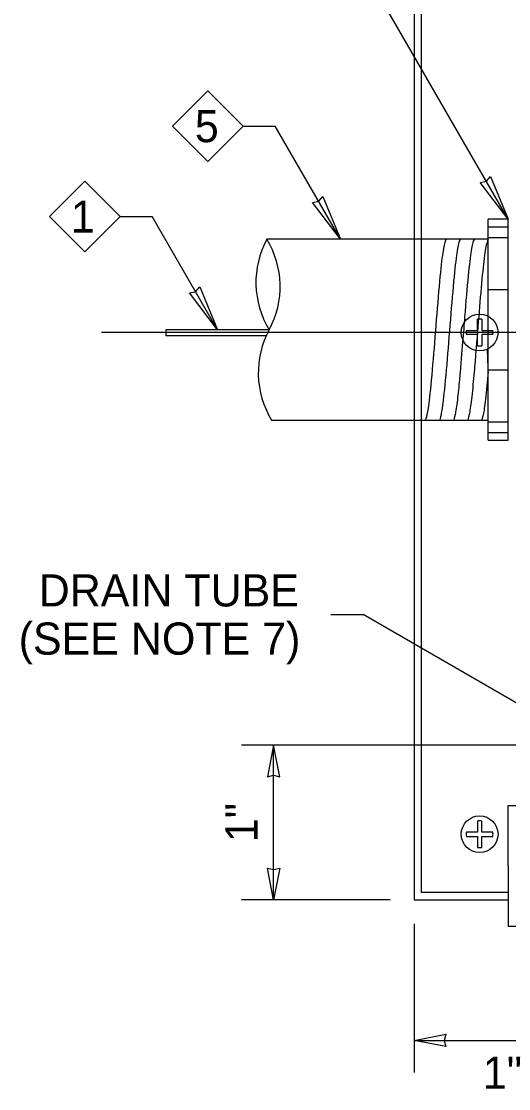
# Model space of a CAD drawing. Extents: x 99862 to 103680, y 99470 to 102076.
# Drawn here: x 101053 to 101296, y 101269 to 101800 of the extents above; entities that cross this region are included whole.
import ezdxf

# ---------------------------------------------------------------- set-up
doc = ezdxf.new("R2010")
doc.units = 0
for name, color, linetype in [('Level 1', 7, 'Continuous'), ('Level 10', 7, 'Continuous'), ('Level 15', 7, 'Continuous'), ('Level 20', 7, 'Continuous'), ('Level 4', 7, 'Continuous'), ('Level 6', 7, 'Continuous'), ('Level 9', 7, 'Continuous')]:
    doc.layers.add(name, color=color, linetype=linetype)

msp = doc.modelspace()

# ---------------------------------------------------------------- linework, layer by layer
at = {"layer": 'Level 1'}
for p, q in [((101248.49, 101927.58), (101248.49, 101362.86)), ((101252.13, 101675.72), (101252.13, 101923.94)), ((101252.13, 101366.5), (101252.13, 101675.72)), ((101295.35, 101366.5), (101252.13, 101366.5)), ((101248.49, 101362.86), (101295.35, 101362.86))]:
    msp.add_line(p, q, dxfattribs=at)
at = {"layer": 'Level 10'}
for p, q in [((101280.05, 101646.21), (101280.05, 101651.78)), ((101282.11, 101651.78), (101282.11, 101646.21)), ((101274.48, 101646.21), (101280.05, 101646.21)), ((101280.05, 101644.15), (101274.48, 101644.15)), ((101280.05, 101638.58), (101280.05, 101644.15)), ((101282.11, 101646.21), (101287.68, 101646.21)), ((101287.68, 101644.15), (101282.11, 101644.15)), ((101282.11, 101644.15), (101282.11, 101638.58)), ((101280.05, 101402.06), (101280.05, 101396.49)), ((101282.11, 101396.49), (101282.11, 101402.06)), ((101280.05, 101396.49), (101274.48, 101396.49)), ((101274.48, 101394.42), (101280.05, 101394.42)), ((101280.05, 101394.42), (101280.05, 101388.86)), ((101287.68, 101396.49), (101282.11, 101396.49)), ((101282.11, 101388.86), (101282.11, 101394.42)), ((101282.11, 101394.42), (101287.68, 101394.42))]:
    msp.add_line(p, q, dxfattribs=at)
for centre in [(101281.08, 101645.18), (101281.08, 101395.46)]:
    msp.add_circle(centre, 9.15, dxfattribs=at)
for centre, start, end in [((101281.08, 101643.18), 83.1584, 96.8416), ((101283.08, 101645.18), 173.1584, 186.8416), ((101279.08, 101645.18), 353.1584, 6.8416), ((101281.08, 101647.18), 263.1584, 276.8416), ((101281.08, 101393.46), 83.1584, 96.8416), ((101283.08, 101395.46), 173.1584, 186.8416), ((101279.08, 101395.46), 353.1584, 6.8416), ((101281.08, 101397.46), 263.1584, 276.8416)]:
    msp.add_arc(centre, 8.66, start, end, dxfattribs=at)
for points in [[(101264.31, 101691.48), (101264, 101690.99), (101263.04, 101687.97), (101261.64, 101676.93), (101259.68, 101654.65), (101257.94, 101631.44), (101255.98, 101610.88), (101254.84, 101603.55), (101254.13, 101601.61), (101254.08, 101601.48)], [(101271.31, 101691.48), (101271, 101690.99), (101270.04, 101687.97), (101268.64, 101676.93), (101266.68, 101654.65), (101264.94, 101631.44), (101262.98, 101610.88), (101261.84, 101603.55), (101261.13, 101601.61), (101261.08, 101601.48)], [(101278.31, 101691.48), (101278, 101690.99), (101277.04, 101687.97), (101275.64, 101676.93), (101273.81, 101656.08), (101272.63, 101640.57), (101271.52, 101627.53)], [(101285.31, 101691.48), (101285, 101690.99), (101284.04, 101687.97), (101282.64, 101676.93), (101280.98, 101658.08), (101279.98, 101645.14), (101279.06, 101633.86)], [(101279.06, 101633.86), (101278.88, 101631.61), (101278.25, 101624.26), (101276.98, 101610.88), (101275.84, 101603.55), (101275.13, 101601.61), (101275.08, 101601.48)], [(101271.52, 101627.53), (101271.52, 101627.45), (101271.08, 101622.38), (101269.98, 101610.88), (101268.84, 101603.55), (101268.13, 101601.61), (101268.08, 101601.48)], [(101285.35, 101625.52), (101284.96, 101621.22), (101283.93, 101610.55), (101282.84, 101603.55), (101282.13, 101601.61), (101282.08, 101601.48)]]:
    msp.add_open_spline(points, degree=3, dxfattribs=at)
at = {"layer": 'Level 15'}
for p, q in [((101295.35, 101701.58), (101208.57, 101851.87)), ((101163.31, 101747.87), (101179.31, 101747.87)), ((101211.81, 101691.58), (101179.31, 101747.87)), ((101102.03, 101702.84), (101118.03, 101702.84)), ((101150.53, 101646.54), (101118.03, 101702.84)), ((102234.36, 101645.22), (101092.77, 101645.22)), ((101207.04, 101504.83), (101223.04, 101504.83)), ((101331.3, 101442.33), (101223.04, 101504.83)), ((101356.63, 101439.83), (101162.49, 101439.83)), ((101178.49, 101362.86), (101178.49, 101439.83)), ((101236.49, 101362.86), (101162.49, 101362.86)), ((101248.49, 101350.86), (101248.49, 101276.87)), ((101248.49, 101292.86), (101335.63, 101292.86))]:
    msp.add_line(p, q, dxfattribs=at)
for points in [[(101295.35, 101701.58), (101281.35, 101719.85), (101284.46, 101720.43), (101286.52, 101722.84)], [(101211.81, 101691.58), (101197.81, 101709.85), (101200.93, 101710.43), (101202.98, 101712.84)], [(101150.53, 101646.54), (101136.53, 101664.82), (101139.65, 101665.4), (101141.7, 101667.81)], [(101178.49, 101439.83), (101175.4, 101424.1), (101178.49, 101424.83), (101181.57, 101424.1)], [(101178.49, 101362.86), (101175.41, 101378.59), (101178.49, 101377.86), (101181.58, 101378.59)], [(101248.49, 101292.86), (101264.21, 101295.95), (101263.48, 101292.86), (101264.21, 101289.78)]]:
    msp.add_lwpolyline(points, close=True, dxfattribs=at)
at = {"layer": 'Level 20'}
for points in [[(101145.76, 101765.42), (101163.31, 101747.87), (101145.76, 101730.31), (101128.21, 101747.87)], [(101084.48, 101720.39), (101102.03, 101702.84), (101084.48, 101685.28), (101066.93, 101702.84)]]:
    msp.add_lwpolyline(points, close=True, dxfattribs=at)
at = {"layer": 'Level 4'}
for p, q in [((101295.35, 101701.54), (101285.35, 101701.54)), ((101285.35, 101591.54), (101285.35, 101701.54)), ((101295.35, 101591.54), (101295.35, 101701.54)), ((101285.35, 101697.78), (101295.35, 101697.78)), ((101248.51, 101691.54), (101175.12, 101691.54)), ((101285.35, 101691.54), (101248.53, 101691.54)), ((101285.35, 101692.37), (101295.35, 101692.37)), ((101285.35, 101666.54), (101295.35, 101666.54)), ((101285.35, 101627.64), (101284.94, 101636.88)), ((101285.35, 101626.54), (101295.35, 101626.54)), ((101177.51, 101601.54), (101248.49, 101601.54)), ((101248.51, 101601.54), (101285.35, 101601.54)), ((101285.35, 101600.72), (101295.35, 101600.72)), ((101285.35, 101595.31), (101295.35, 101595.31)), ((101285.35, 101591.54), (101295.35, 101591.54))]:
    msp.add_line(p, q, dxfattribs=at)
for centre, start, end in [((101214.67, 101670.08), 151.511, 211.511), ((101136.75, 101668.02), 331.511, 31.511), ((101215.85, 101625.09), 151.511, 211.5578)]:
    msp.add_arc(centre, 45, start, end, dxfattribs=at)
at = {"layer": 'Level 6'}
for p, q in [((101295.35, 101379.72), (101295.35, 101409.72)), ((101295.35, 101409.72), (101355.35, 101409.72)), ((101295.35, 101379.72), (101295.35, 101349.72)), ((101295.35, 101349.72), (101300.35, 101349.72))]:
    msp.add_line(p, q, dxfattribs=at)
at = {"layer": 'Level 9'}
for p, q in [((101124.77, 101646.54), (101124.77, 101643.54)), ((101176.3, 101646.54), (101124.77, 101646.54)), ((101174.81, 101643.54), (101124.77, 101643.54))]:
    msp.add_line(p, q, dxfattribs=at)

# ---------------------------------------------------------------- texts
at = {"layer": 'Level 20'}
for s, p in [('5', (101139.27, 101739.87)), ('1', (101077.53, 101694.84)), ('DRAIN TUBE', (101061.51, 101508.83)), ('(SEE NOTE 7)', (101051.53, 101484.83)), ('1"', (101282.69, 101268.86))]:
    msp.add_text(s, height=16, dxfattribs=at).set_placement(p)
msp.add_text('1"', height=16, rotation=90, dxfattribs=at).set_placement((101170.49, 101391.53))

doc.saveas('drawing.dxf')
